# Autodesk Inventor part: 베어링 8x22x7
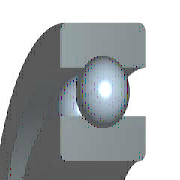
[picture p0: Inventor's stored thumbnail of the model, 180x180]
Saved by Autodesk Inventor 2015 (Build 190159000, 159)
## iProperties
IsCustomPart: 1
Created: 2012-02
Part Number: 베어링 8x22x7
Material: 강철, 연강
Description: 깊은 그루브 볼 베어링
Document SubType Name: Modeling
Standard: KS B 2023
Designer: mduedu
Standards Organization: KS
Language: ko-KR
Size Designation: 608 - 8 x 22 x 7
Categories: <MemberInstance><Categories><Category DisplayName="샤프트 부품" InternalName="7f7aeb1f-a693-4053-b835-cee3144e0d98" Mnemonic="SHFT"><Category DisplayName="베어링" Inter
Density: 7.85 g/cm^3
Appearance: 노란색
Mass: 12.145 g
Surface Area: 20.0754 cm^2
Volume: 1.54714 cm^3
Author: mduedu
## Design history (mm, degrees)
sketch "스케치" dims "d0" = 3.64 (= -0.26 x WD + 0.26 x BD)
  geometry: L1 (1.68, 7.5)-(5.32, 7.5); L2 (3.5, 7.5)-(3.5, 5.68); L3 (3.5, 7.5)-(3.5, 9.32); L4 (2.148, 6.282)-(0, 6.282); L5 (0, 4)-(7, 4); L6 (2.148, 8.718)-(0, 8.718); L7 (0, 11)-(7, 11); L8 (7, 4)-(7, 6.282); L9 (4.852, 6.282)-(7, 6.282); L10 (4.852, 8.718)-(7, 8.718); L11 (7, 11)-(7, 8.718); L12 (-1.4, 0)-(8.4, 0) reference; L13 (0, -0.3)-(0, 5.3) reference
  constraints: 22 end point, 4 point on line, 2 collinear, 2 perpendicular, 2 symmetric about line, 1 midpoint, 1 parallel, 14 other
  dimensions: "d9" = 8 diameter of L5 L12 (= WD); "d11" = 22 diameter of L7 L12 (= BD); "d12" = 7 distance between parallel lines of L8 L13 (= KB); "d13" = 12.564 diameter of L9 L12 (= 0.326 x BD + 0.674 x WD)
revolve "본체" stored, may be unused: angle "d6" = 90 deg
revolve "볼" stored, may be unused: angle "d7" = 90 deg
pattern_circular "IDS_ARRAYBALL[SIMPL:T]" dims angle "d3" = 360 deg
body "Solid1"
fillet "모깎기1" dims "d1" = 0.3 (= KRS)
other parameters: "WD" = 8 [user parameter; used in 5 equation terms], "BD" = 22 [user parameter; used in 5 equation terms], "KB" = 7 [user parameter; used in 1 equation term], "KRS" = 0.3 [user parameter; used in 1 equation term], "d4" = 0, "d5" = 0, "d8" = 0, "d14" = 0, "d15" = 0, "BBA" = 0 [user parameter], "BC0" = 1370000 [user parameter], "BC" = 3250000 [user parameter], "BR" = 11 (= 0.5 x BD) [user parameter], "WR" = 4 (= 0.5 x WD) [user parameter]
